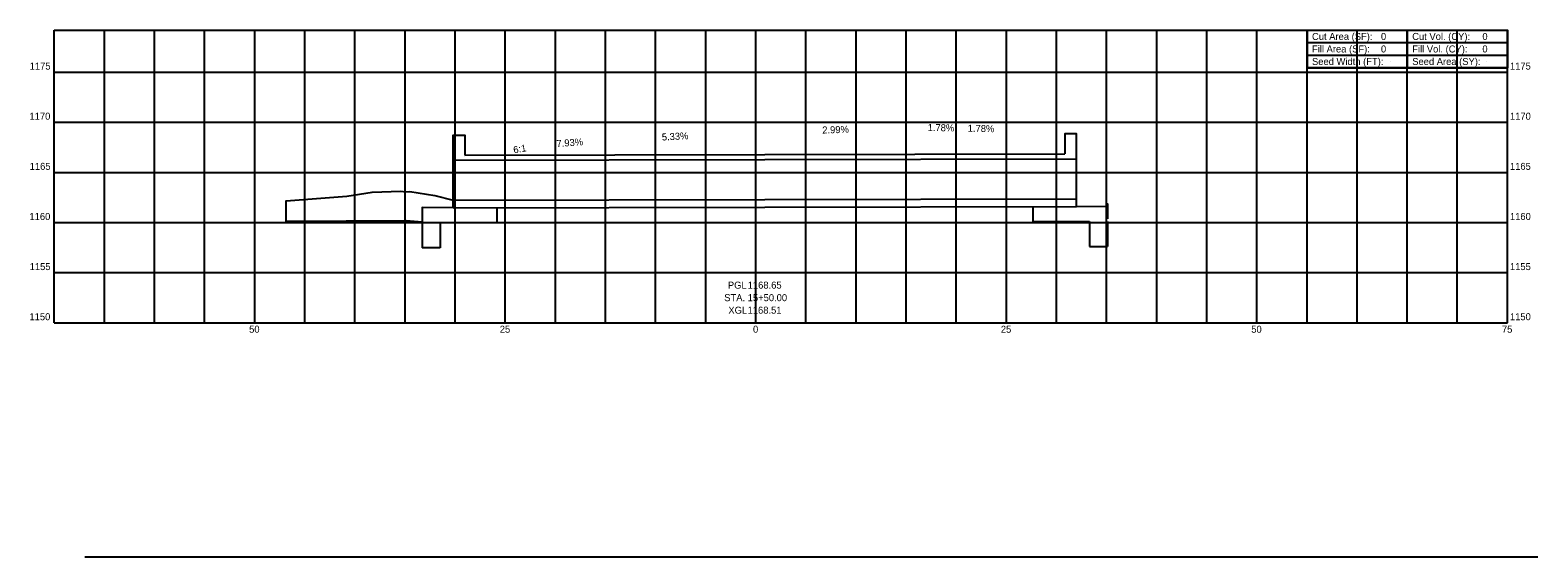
# Model space of a CAD drawing. Extents: x -72 to 78, y 1127 to 1179.
import ezdxf

# ---------------------------------------------------------------- set-up
doc = ezdxf.new("R2010")
doc.units = 0
for name, color, linetype in [('Default', 7, 'Continuous'), ('GE_P_Alignment', 7, 'Continuous'), ('RW_P_CL', 7, 'Continuous'), ('RW_P_CL_100_Bearings', 7, 'Continuous'), ('RW_P_CL_100_Cardinal_Points', 7, 'Continuous'), ('SH_Data', 7, 'Continuous'), ('SH_Major_Grid_Line', 7, 'Continuous'), ('SH_Masking', 7, 'Continuous'), ('SH_Text', 7, 'Continuous')]:
    doc.layers.add(name, color=color, linetype=linetype)

msp = doc.modelspace()

# ---------------------------------------------------------------- linework, layer by layer
at = {"layer": 'Default'}
msp.add_circle((75, 1179.19), 0.000417, dxfattribs=at)
msp.add_circle((75, 1179.19), 0.000417, dxfattribs=at)
msp.add_circle((75, 1179.19), 0.000417, dxfattribs=at)
msp.add_circle((75, 1179.19), 0.000417, dxfattribs=at)
msp.add_circle((75, 1179.19), 0.000417, dxfattribs=at)
msp.add_circle((75, 1179.19), 0.000417, dxfattribs=at)
msp.add_circle((75, 1179.19), 0.000417, dxfattribs=at)
msp.add_circle((75, 1179.19), 0.000417, dxfattribs=at)
msp.add_circle((75, 1179.19), 0.000417, dxfattribs=at)
msp.add_circle((75, 1179.19), 0.000417, dxfattribs=at)
msp.add_circle((75, 1179.19), 0.000417, dxfattribs=at)
msp.add_circle((75, 1179.19), 0.000417, dxfattribs=at)
at = {"layer": 'GE_P_Alignment'}
msp.add_lwpolyline([(-34.88, 1160.17), (-46.85, 1160.09), (-46.85, 1162.16), (-40.8, 1162.61), (-38.29, 1163.03), (-35.41, 1163.13), (-34.93, 1163.06), (-34.52, 1163.09), (-32.03, 1162.69), (-30.21, 1162.22), (-30.21, 1161.47), (-33.28, 1161.48), (-33.28, 1160.02)], close=True, dxfattribs=at)
at = {"layer": 'RW_P_CL'}
for p, q in [((-30.21, 1161.47), (-33.28, 1161.48)), ((-25.85, 1161.46), (-25.85, 1159.95)), ((27.65, 1161.6), (27.65, 1160.09)), ((32.01, 1161.61), (35.08, 1161.62)), ((-25.85, 1159.95), (-31.5, 1159.97)), ((-31.5, 1159.97), (-31.5, 1157.47)), ((27.65, 1160.09), (33.3, 1160.11)), ((33.3, 1160.11), (33.3, 1157.61)), ((35.08, 1160.11), (35.08, 1157.61)), ((-33.28, 1159.6), (-33.28, 1157.47)), ((-31.5, 1157.47), (-33.28, 1157.47)), ((33.3, 1157.61), (35.08, 1157.61))]:
    msp.add_line(p, q, dxfattribs=at)
for points in [[(-33.28, 1161.48), (-33.28, 1161.48), (-33.28, 1159.6)], [(35.08, 1161.87), (35.08, 1161.87), (35.08, 1160.37)]]:
    msp.add_lwpolyline(points, dxfattribs=at)
at = {"layer": 'RW_P_CL_100_Bearings'}
for p, q in [((-30.21, 1166.22), (32.01, 1166.36)), ((-29.02, 1166.72), (30.82, 1166.86)), ((-30.21, 1162.22), (32.01, 1162.36)), ((-30.21, 1161.47), (32.01, 1161.61))]:
    msp.add_line(p, q, dxfattribs=at)
at = {"layer": 'RW_P_CL_100_Cardinal_Points'}
for points in [[(-30.21, 1161.47), (-30.21, 1168.72), (-29.02, 1168.72), (-29.02, 1166.72)], [(32.01, 1161.61), (32.01, 1168.86), (30.82, 1168.86), (30.82, 1166.86)]]:
    msp.add_lwpolyline(points, dxfattribs=at)
at = {"layer": 'SH_Data'}
for p, q in [((55, 1179.19), (75, 1179.19)), ((55, 1179.19), (55, 1176.69)), ((65, 1179.19), (65, 1175.44)), ((75, 1179.19), (75, 1176.69)), ((55, 1177.94), (75, 1177.94)), ((55, 1176.69), (75, 1176.69)), ((63.3, 1176.06), (63.3, 1176.06)), ((72.95, 1176.06), (72.95, 1176.06))]:
    msp.add_line(p, q, dxfattribs=at)
msp.add_lwpolyline([(55, 1176.69), (55, 1175.44), (75, 1175.44), (75, 1176.69)], dxfattribs=at)
at = {"layer": 'SH_Major_Grid_Line'}
for p, q in [((-70, 1179.19), (75, 1179.19)), ((-70, 1150), (-70, 1179.19)), ((-65, 1150), (-65, 1179.19)), ((-60, 1150), (-60, 1179.19)), ((-55, 1150), (-55, 1179.19)), ((-50, 1150), (-50, 1179.19)), ((-45, 1150), (-45, 1179.19)), ((-40, 1150), (-40, 1179.19)), ((-35, 1150), (-35, 1179.19)), ((-30, 1150), (-30, 1179.19)), ((-25, 1150), (-25, 1179.19)), ((-20, 1150), (-20, 1179.19)), ((-15, 1150), (-15, 1179.19)), ((-10, 1150), (-10, 1179.19)), ((-5, 1150), (-5, 1179.19)), ((0, 1150), (0, 1179.19)), ((5, 1150), (5, 1179.19)), ((10, 1150), (10, 1179.19)), ((15, 1150), (15, 1179.19)), ((20, 1150), (20, 1179.19)), ((25, 1150), (25, 1179.19)), ((30, 1150), (30, 1179.19)), ((35, 1150), (35, 1179.19)), ((40, 1150), (40, 1179.19)), ((45, 1150), (45, 1179.19)), ((50, 1150), (50, 1179.19)), ((55, 1150), (55, 1179.19)), ((60, 1150), (60, 1179.19)), ((65, 1150), (65, 1179.19)), ((70, 1150), (70, 1179.19)), ((75, 1150), (75, 1179.19)), ((-70, 1175), (75, 1175)), ((-70, 1170), (75, 1170)), ((-70, 1164.99), (75, 1164.99)), ((-70, 1160), (75, 1160)), ((-70, 1155), (75, 1155)), ((-70, 1150), (75, 1150)), ((-66.97, 1126.64), (78.03, 1126.64))]:
    msp.add_line(p, q, dxfattribs=at)
at = {"layer": 'SH_Masking'}
msp.add_lwpolyline([(55, 1179.19), (75, 1179.19), (75, 1175.44), (55, 1175.44)], close=True, dxfattribs=at)

# ---------------------------------------------------------------- texts
at = {"layer": 'SH_Text'}
for s, p in [('Cut Area (SF):', (55.5, 1178.21)), ('0', (62.38, 1178.21)), ('Cut Vol. (CY):', (65.5, 1178.21)), ('0', (72.5, 1178.21)), ('Fill Area (SF):', (55.5, 1176.96)), ('0', (62.38, 1176.96)), ('Fill Vol. (CY):', (65.5, 1176.96)), ('0', (72.5, 1176.96)), ('1175', (-72.46, 1175.25)), ('Seed Width (FT):', (55.5, 1175.71)), ('Seed Area (SY):', (65.5, 1175.71)), ('1175', (75.25, 1175.25)), ('1170', (-72.48, 1170.25)), ('1170', (75.25, 1170.25)), ('1165', (-72.46, 1165.25)), ('1165', (75.25, 1165.25)), ('1160', (-72.48, 1160.25)), ('1160', (75.25, 1160.25)), ('1155', (-72.46, 1155.25)), ('1155', (75.25, 1155.25)), ('PGL ', (-2.79, 1153.4)), ('1168.65', (-0.81, 1153.4)), ('STA. 15+50.00', (-3.15, 1152.15)), ('1150', (-72.48, 1150.25)), ('XGL ', (-2.74, 1150.9)), ('1168.51', (-0.82, 1150.9)), ('1150', (75.25, 1150.25)), ('50', (-50.56, 1149)), ('25', (-25.55, 1149)), ('0', (-0.28, 1149)), ('25', (24.45, 1149)), ('50', (49.44, 1149)), ('75', (74.45, 1149))]:
    msp.add_text(s, height=0.7, dxfattribs=at).set_placement(p)
for s, rotation, p in [('5.33%', 3.0497, (-9.36, 1168.17)), ('2.99%', 1.7111, (6.64, 1168.87)), ('1.78%', 358.9828, (17.14, 1169.13)), ('1.78%', 358.9828, (21.14, 1169.05)), ('6:1', 9.4623, (-24.14, 1166.89)), ('7.93%', 4.5356, (-19.86, 1167.51))]:
    msp.add_text(s, height=0.7, rotation=rotation, dxfattribs=at).set_placement(p)

doc.saveas('drawing.dxf')
